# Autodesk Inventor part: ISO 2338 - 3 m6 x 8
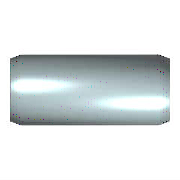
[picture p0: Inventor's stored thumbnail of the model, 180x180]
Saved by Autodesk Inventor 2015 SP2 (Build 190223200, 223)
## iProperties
IsCustomPart: 0
Created: 2012-02
Part Number: ISO 2338 - 3 m6 x 8
Material: Stainless Steel, Austenitic
Description: Parallel Pin
Document SubType Name: Modeling
Standard: ISO 2338
Designer: rYan
Standards Organization: DIN
Language: en-US
Size Designation: 3 m6 x 8
Categories: <MemberInstance><Categories><Category DisplayName="Fasteners" InternalName="e4da775c-781d-43d5-af7c-5136215cf5a6" Mnemonic="FSTN"><Category DisplayName="Pins" I
Density: 8.03 g/cm^3
Appearance: Halbpoliert
Author: rYan
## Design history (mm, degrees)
sketch "Sketch"
  geometry: C1 r 1.5 at (0, 0); 1 further point
  constraints: 1 centre point, 1 coincident
  dimensions: "d1" = 3 diameter of C1 (= NND)
extrude "Body" new body sketch "Sketch" distance "d2" = 8 (= NLG); taper "d3" = 0 deg
chamfer "Chamfer1" distance "d4" = 0.5 (= PHH); stored, may be unused: angle "d5" = 15 deg (= FAWI), second distance "d11" = 0.5 (= PHH)
chamfer "Chamfer2" distance "d8" = 0.5 (= PHH); stored, may be unused: angle "d9" = 15 deg (= FAWI), second distance "d12" = 0.5 (= PHH)
body "Solid1"
other parameters: "NND" = 3 [user parameter; used in 1 equation term], "NLG" = 8 [user parameter; used in 1 equation term], "PHH" = 0.5 [user parameter; used in 4 equation terms], "FAWI" = 15 deg [user parameter; used in 2 equation terms], "d13" = 0, "d15" = 0, "d16" = 0, "KAH" = 0 [user parameter]
